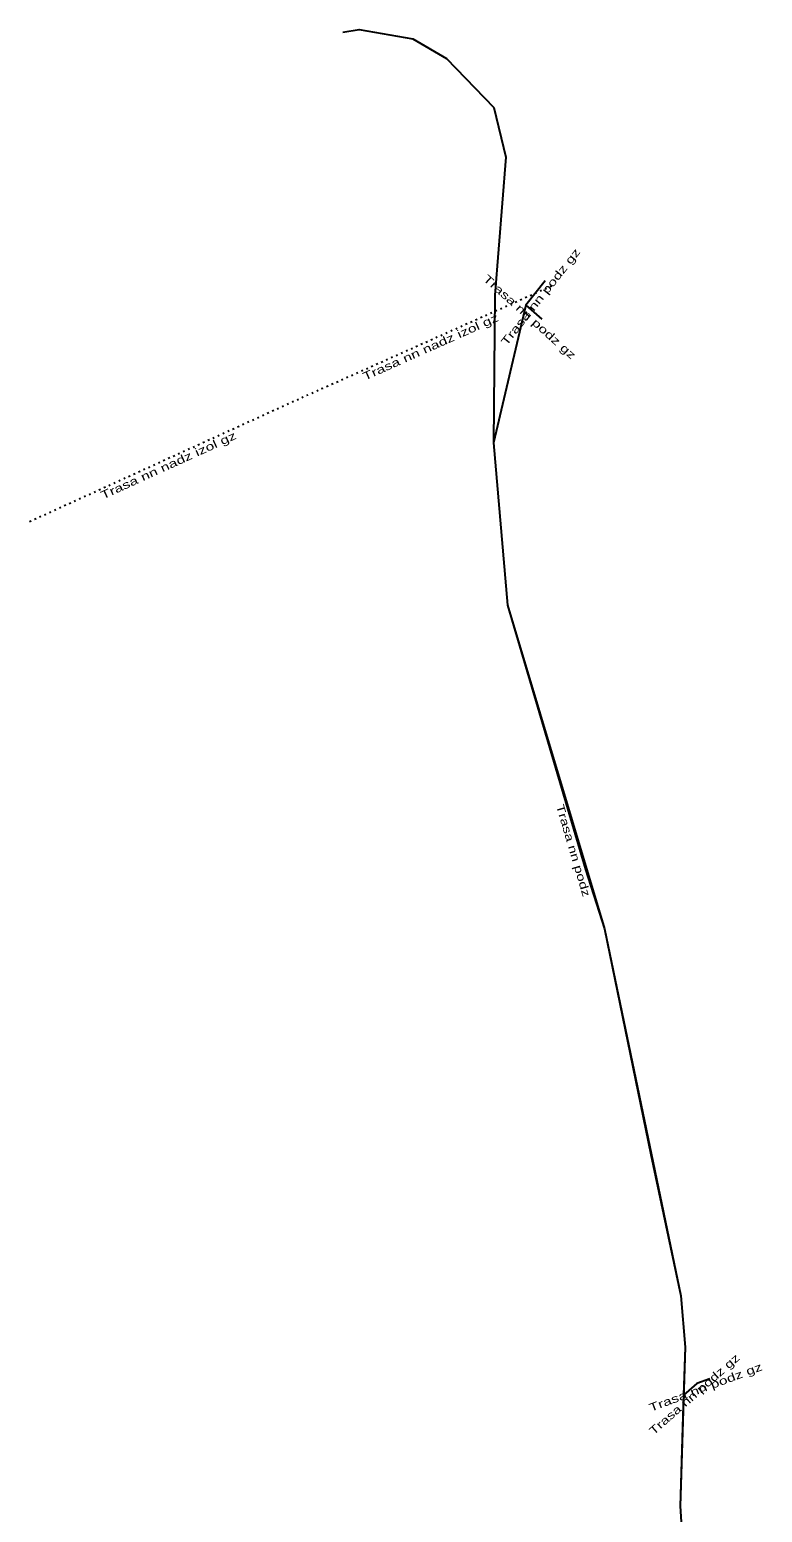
# Model space of a CAD drawing. Extents: x -810379 to -809541, y -1032744 to -1032173.
# Drawn here: x -810314.5 to -810268.7, y -1032334.9 to -1032242.3 of the extents above; entities that cross this region are included whole.
import ezdxf
from ezdxf.enums import TextEntityAlignment as Align

# ---------------------------------------------------------------- set-up
doc = ezdxf.new("R2010")
doc.units = 0
doc.header["$LTSCALE"] = 0.2
doc.linetypes.add('DOTTED', pattern=[1.5, 0.3, -1.2])
doc.layers.add('11', color=7, linetype='Continuous', lineweight=25)
doc.layers.add('21', color=7, linetype='Continuous', lineweight=25)
doc.layers.add('20', color=7, linetype='Continuous')

msp = doc.modelspace()

# ---------------------------------------------------------------- linework, layer by layer
at = {"layer": '11', "linetype": 'DOTTED'}
for p, q in [((-810297.48, -1032265.29), (-810281.71, -1032258.24)), ((-810314.49, -1032273.03), (-810297.48, -1032265.29))]:
    msp.add_line(p, q, dxfattribs=at)
at = {"layer": '11'}
for points in [[(-810282.27, -1032257.99), (-810283.47, -1032259.51), (-810282.48, -1032260.4)], [(-810283.47, -1032259.51), (-810285.502, -1032268.125), (-810284.612, -1032278.261), (-810279.745, -1032294.769), (-810278.566, -1032298.48), (-810275.656, -1032312.575), (-810273.792, -1032321.404), (-810273.515, -1032324.63), (-810273.62, -1032327.623)], [(-810271.973, -1032326.59), (-810272.794, -1032326.897), (-810273.62, -1032327.623)], [(-810273.62, -1032327.623), (-810273.686, -1032329.588), (-810273.823, -1032334.563), (-810273.182, -1032344.772), (-810272.901, -1032351.876)]]:
    msp.add_lwpolyline(points, dxfattribs=at)
at = {"layer": '21'}
msp.add_lwpolyline([(-810294.921, -1032242.459), (-810293.889, -1032242.305), (-810290.531, -1032242.883), (-810288.424, -1032244.104), (-810285.479, -1032247.174), (-810284.728, -1032250.281), (-810285.411, -1032258.902), (-810285.502, -1032268.125), (-810284.612, -1032278.261), (-810278.566, -1032298.48), (-810273.792, -1032321.404), (-810273.515, -1032324.63), (-810273.823, -1032334.563), (-810273.182, -1032344.772)], dxfattribs=at)

# ---------------------------------------------------------------- texts
at = {"layer": '20'}
for s, rotation, width, p in [('Trasa nn podz gz', 51.71, 1.45, (-810282.3589, -1032259.1524)), ('Trasa nn podz gz', 318.045, 1.45, (-810283.4086, -1032260.4373)), ('Trasa nn nadz izol gz', 24.087, 1.45, (-810289.3295, -1032262.3571)), ('Trasa nn nadz izol gz', 24.467, 1.45, (-810305.715, -1032269.7514)), ('Trasa nn podz', 286.427, 1.4, (-810280.7492, -1032293.6598)), ('Trasa nn podz gz', 41.322, 1.4, (-810272.7776, -1032327.7472)), ('Trasa nn podz gz', 20.491, 1.45, (-810272.155, -1032327.352))]:
    msp.add_text(s, height=0.5, rotation=rotation, dxfattribs=dict(at, width=width)).set_placement(p, align=Align.CENTER)

doc.saveas('drawing.dxf')
